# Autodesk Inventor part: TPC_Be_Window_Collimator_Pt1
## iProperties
Shininess: 64.0
Length Units: 11269
Angle Units: 11279
Time Units: 11290
Mass Units: 11283
Length Display Precision: 3
Angle Display Precision: 2
Compacted: True
Part Number: TPC_Be_Window_Collimator_Pt1
Document SubType Name: Modeling
Created: 2004-07
Project: Mucap
Material: Stainless Steel, Austenitic
Description: Mucap, Be Window Collimator
Designer: John Blackburn
Manufacturer: Standard
Standards Organization: Custom
Density: 0.0
Volumn: 0.0
Area: 0.0
PropertySet Name: Model Information
Control State: 0
Master: False
Checked Out: False
Title: Mucap, Be Window Collimator
Subject: Mucap
Author: John Blackburn
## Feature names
1. Revolution1
2. Hole1
3. Circular Pattern1
4. Extrusion1
5. Hole2
6. Circular Pattern2
